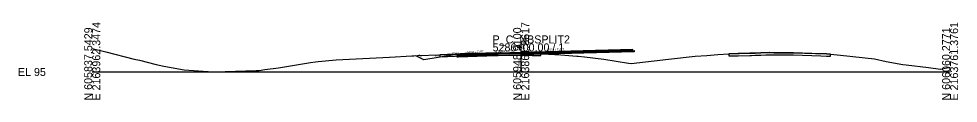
# Model space of a CAD drawing. Extents: x -26 to 1303, y -10 to 12038.
# Drawn here: x -25.7 to 302.8, y 3490.3 to 3517.4 of the extents above; entities that cross this region are included whole.
import ezdxf

# ---------------------------------------------------------------- set-up
doc = ezdxf.new("R2010")
doc.units = 0
for name, color, linetype in [('RD_GPK_XS_Cell', 7, 'Continuous'), ('RD_XS_Base', 7, 'Continuous'), ('RD_XS_ExGround', 7, 'Continuous'), ('RD_XS_ExPaveRet', 7, 'Continuous'), ('RD_XS_Greenside', 7, 'Continuous'), ('RD_XS_Pave', 7, 'Continuous'), ('RD_XS_PaveOvlay_CP', 7, 'Continuous'), ('RD_XS_TieSlope', 7, 'Continuous'), ('RD_XS_TX_Elev_EX', 7, 'Continuous'), ('RD_XS_TX_Elev_PR', 7, 'Continuous'), ('RD_XS_TX_ShdSlope', 7, 'Continuous'), ('RD_XS_TX_Slope', 7, 'Continuous')]:
    doc.layers.add(name, color=color, linetype=linetype)

msp = doc.modelspace()

# ---------------------------------------------------------------- linework, layer by layer
at = {"layer": 'RD_GPK_XS_Cell'}
for p, q in [((150, 3500), (150, 3510)), ((0, 3500), (150, 3500)), ((150, 3500), (300, 3500))]:
    msp.add_line(p, q, dxfattribs=at)
at = {"layer": 'RD_XS_Base'}
for p, q in [((128, 3505.77), (127.5, 3505.75)), ((127.5, 3505.75), (127.5, 3505.75)), ((127.5, 3505.75), (127.5, 3505.25)), ((138, 3506.17), (128, 3505.77)), ((128, 3505.77), (128, 3505.77)), ((128, 3505.27), (138, 3505.67)), ((150, 3506.48), (138, 3506.17)), ((138, 3506.17), (138, 3506.17)), ((138, 3505.67), (150, 3505.98)), ((138, 3505.67), (138, 3505.67)), ((150, 3506.48), (189.53, 3507.51)), ((189.53, 3507.01), (150, 3505.98)), ((150, 3505.98), (150, 3506.64)), ((150, 3506.64), (150, 3506.64)), ((150, 3506.64), (150, 3506.64)), ((150, 3506.64), (150, 3506.48)), ((150, 3506.48), (150, 3506.48)), ((150, 3505.98), (150, 3506.48)), ((150, 3506.48), (150, 3506.48)), ((150, 3506.48), (150, 3506.48)), ((150, 3505.98), (150, 3505.98)), ((174, 3507.11), (174, 3507.11)), ((174, 3507.11), (174, 3507.11)), ((174, 3506.61), (174, 3506.61)), ((174, 3506.61), (174, 3506.61)), ((189.03, 3507.5), (189.03, 3507.5)), ((189.53, 3507.51), (189.53, 3507.01)), ((189.53, 3507.48), (189.53, 3507.48)), ((127.5, 3505.25), (128, 3505.27)), ((128, 3505.27), (128, 3505.27))]:
    msp.add_line(p, q, dxfattribs=at)
at = {"layer": 'RD_XS_ExGround'}
msp.add_lwpolyline([(0, 3508.19), (4.75, 3507), (14.63, 3504.54), (16.49, 3504.08), (22.3, 3502.63), (25.03, 3502.08), (32.19, 3500.73), (42.14, 3500.03), (42.45, 3500.01), (42.57, 3500.01), (42.84, 3500.02), (57.27, 3500.5), (58.38, 3500.55), (60.32, 3500.84), (65.17, 3501.5), (76.32, 3503.33), (78.02, 3503.6), (79.04, 3503.71), (85.3, 3504.28), (103.91, 3505.24), (111.79, 3505.61), (112.44, 3505.67), (113.75, 3505.71), (121.56, 3506.04), (126.92, 3506.27), (130.28, 3506.41), (133.12, 3506.47), (134.35, 3506.5), (137.6, 3506.55), (139.92, 3506.58), (141.24, 3506.6), (141.76, 3506.64), (153.87, 3506.51), (156.91, 3506.46), (159.56, 3506.27), (163.84, 3505.95), (169.47, 3505.51), (169.94, 3505.5), (172.12, 3505.25), (178.85, 3504.5), (187.58, 3503.13), (188.41, 3502.99), (201.47, 3504.5), (201.47, 3504.5), (201.47, 3504.5), (210.88, 3505.5), (214.93, 3505.82), (218.73, 3506.09), (222.62, 3506.38), (229.98, 3506.55), (231.79, 3506.59), (233.83, 3506.67), (236.82, 3506.76), (236.92, 3506.76), (238.38, 3506.74), (242.46, 3506.75), (245.23, 3506.71), (256.76, 3506.33), (258.22, 3506.27), (261.63, 3505.91), (273.59, 3504.59), (277.6, 3503.72), (283.49, 3502.58), (284.6, 3502.5), (292.48, 3501.53), (296.6, 3501.04), (300, 3501.73)], dxfattribs=at)
at = {"layer": 'RD_XS_ExPaveRet'}
for points in [[(156.91, 3506.46), (156.91, 3506.46), (153.87, 3506.51), (153.87, 3506.51), (141.76, 3506.64), (141.24, 3506.6), (141.24, 3506.6), (141.24, 3506.6), (139.92, 3506.58), (139.92, 3506.58), (137.6, 3506.55), (137.6, 3506.55), (134.35, 3506.5), (134.35, 3506.5), (133.12, 3506.47), (133.12, 3506.47), (130.28, 3506.41), (126.92, 3506.27), (126.92, 3506.27), (121.56, 3506.04), (121.56, 3506.04), (121.56, 3506.04), (121.56, 3505.29), (121.56, 3505.29), (126.92, 3505.52), (126.92, 3505.52), (130.28, 3505.66), (133.12, 3505.72), (133.12, 3505.72), (134.35, 3505.75), (134.35, 3505.75), (137.6, 3505.8), (137.6, 3505.8), (139.92, 3505.83), (139.92, 3505.83), (141.24, 3505.85), (141.24, 3505.85), (141.24, 3505.85), (141.76, 3505.89), (153.87, 3505.76), (153.87, 3505.76), (156.91, 3505.71), (156.91, 3505.71), (156.91, 3505.71), (156.91, 3506.46), (156.91, 3506.46), (156.91, 3506.46)], [(156.91, 3506.46), (153.87, 3506.51), (141.76, 3506.64), (141.24, 3506.6), (139.92, 3506.58), (137.6, 3506.55), (134.35, 3506.5), (133.12, 3506.47), (130.28, 3506.41), (126.92, 3506.27), (121.56, 3506.04), (121.56, 3505.29), (126.92, 3505.52), (130.28, 3505.66), (133.12, 3505.72), (134.35, 3505.75), (137.6, 3505.8), (139.92, 3505.83), (141.24, 3505.85), (141.76, 3505.89), (153.87, 3505.76), (156.91, 3505.71), (156.91, 3505.71), (156.91, 3506.46), (156.91, 3506.46)], [(256.76, 3506.33), (254.81, 3506.4), (245.23, 3506.71), (242.97, 3506.75), (242.46, 3506.75), (241, 3506.75), (238.38, 3506.74), (237.85, 3506.75), (236.92, 3506.76), (236.86, 3506.76), (236.82, 3506.76), (235.53, 3506.72), (233.83, 3506.67), (232.43, 3506.62), (231.79, 3506.59), (230.59, 3506.56), (229.98, 3506.55), (225.86, 3506.45), (222.62, 3506.38), (222.62, 3506.08), (222.62, 3505.63), (225.86, 3505.7), (229.98, 3505.8), (230.59, 3505.81), (231.79, 3505.84), (232.43, 3505.87), (233.83, 3505.92), (235.53, 3505.97), (236.82, 3506.01), (236.86, 3506.01), (236.92, 3506.01), (237.85, 3506), (238.38, 3505.99), (241, 3506), (242.46, 3506), (242.97, 3506), (245.23, 3505.96), (254.81, 3505.65), (256.76, 3505.58), (258.22, 3505.52), (258.22, 3505.6), (258.22, 3506.27), (256.76, 3506.33)], [(256.76, 3506.33), (254.81, 3506.4), (245.23, 3506.71), (242.97, 3506.75), (242.46, 3506.75), (241, 3506.75), (238.38, 3506.74), (237.85, 3506.75), (236.92, 3506.76), (236.86, 3506.76), (236.82, 3506.76), (235.53, 3506.72), (233.83, 3506.67), (232.43, 3506.62), (231.79, 3506.59), (230.59, 3506.56), (229.98, 3506.55), (225.86, 3506.45), (222.62, 3506.38), (222.62, 3506.08), (222.62, 3505.63), (225.86, 3505.7), (229.98, 3505.8), (230.59, 3505.81), (231.79, 3505.84), (232.43, 3505.87), (233.83, 3505.92), (235.53, 3505.97), (236.82, 3506.01), (236.86, 3506.01), (236.92, 3506.01), (237.85, 3506), (238.38, 3505.99), (241, 3506), (242.46, 3506), (242.97, 3506), (245.23, 3505.96), (254.81, 3505.65), (256.76, 3505.58), (258.22, 3505.52), (258.22, 3505.6), (258.22, 3506.27), (256.76, 3506.33)]]:
    msp.add_lwpolyline(points, dxfattribs=at)
at = {"layer": 'RD_XS_Greenside'}
for p, q in [((116, 3504.26), (113.14, 3505.69)), ((126, 3505.93), (116, 3504.26))]:
    msp.add_line(p, q, dxfattribs=at)
at = {"layer": 'RD_XS_Pave'}
for p, q in [((138, 3506.49), (128, 3506.09)), ((128, 3505.93), (138, 3506.33)), ((138, 3506.33), (128, 3505.93)), ((128, 3505.77), (138, 3506.17)), ((128, 3506.09), (128, 3506.09)), ((128, 3506.09), (128, 3505.93)), ((128, 3505.93), (128, 3505.93)), ((128, 3505.93), (128, 3505.77)), ((150, 3506.8), (138, 3506.49)), ((138, 3506.33), (150, 3506.64)), ((150, 3506.64), (138, 3506.33)), ((138, 3506.49), (138, 3506.49)), ((138, 3506.17), (150, 3506.48)), ((138, 3506.33), (138, 3506.33)), ((138, 3506.33), (138, 3506.33)), ((138, 3506.17), (138, 3506.17)), ((189.03, 3507.82), (150, 3506.8)), ((189.03, 3507.66), (150, 3506.64)), ((150, 3506.48), (189.03, 3507.5)), ((150, 3506.8), (150, 3506.8)), ((150, 3506.64), (150, 3506.64)), ((150, 3506.64), (150, 3506.64)), ((150, 3506.64), (150, 3506.48)), ((150, 3506.64), (150, 3506.64)), ((150, 3506.48), (150, 3506.64)), ((150, 3506.64), (150, 3506.64)), ((150, 3506.64), (150, 3506.64)), ((150, 3506.48), (150, 3506.48)), ((150, 3506.48), (150, 3506.48)), ((174, 3507.43), (174, 3507.43)), ((174, 3507.43), (174, 3507.43)), ((174, 3507.27), (174, 3507.27)), ((174, 3507.27), (174, 3507.27)), ((174, 3507.27), (174, 3507.27)), ((174, 3507.27), (174, 3507.27)), ((174, 3507.11), (174, 3507.11)), ((174, 3507.11), (174, 3507.11)), ((189.03, 3507.66), (189.03, 3507.82)), ((189.03, 3507.82), (189.03, 3507.82)), ((189.03, 3507.5), (189.03, 3507.66)), ((189.03, 3507.66), (189.03, 3507.66))]:
    msp.add_line(p, q, dxfattribs=at)
at = {"layer": 'RD_XS_PaveOvlay_CP'}
for p, q in [((138, 3506.49), (128, 3506.09)), ((150, 3506.8), (138, 3506.49)), ((138, 3506.49), (138, 3506.49)), ((189.03, 3507.82), (150, 3506.8)), ((150, 3506.8), (150, 3506.8)), ((174, 3507.43), (174, 3507.43)), ((174, 3507.43), (174, 3507.43))]:
    msp.add_line(p, q, dxfattribs=at)
at = {"layer": 'RD_XS_TieSlope'}
msp.add_line((128, 3506.09), (126, 3505.93), dxfattribs=at)

# ---------------------------------------------------------------- texts
at = {"layer": 'RD_GPK_XS_Cell'}
for s, p in [('N 605837.5429', (0, 3490)), ('E 2163962.3474', (2.8, 3490)), ('N 605948.9100', (150, 3490)), ('E 2163861.8617', (152.8, 3490)), ('N 606060.2771', (300, 3490)), ('E 2163761.3761', (302.8, 3490))]:
    msp.add_text(s, height=2.8, rotation=90, dxfattribs=at).set_placement(p)
for s, p in [('P_C_NBSPLIT2', (140, 3510)), ('5286+00.00 / 1', (140, 3507.2)), ('EL 95', (-26, 3498.6))]:
    msp.add_text(s, height=2.8, dxfattribs=at).set_placement(p)
at = {"layer": 'RD_XS_TX_Elev_EX'}
msp.add_text('101.56', height=0.6, rotation=90, dxfattribs=at).set_placement((149.72, 3507.36))
at = {"layer": 'RD_XS_TX_Elev_PR'}
msp.add_text('101.80', height=1, rotation=90, dxfattribs=at).set_placement((151.37, 3507.16))
at = {"layer": 'RD_XS_TX_ShdSlope'}
msp.add_text('12.5:1', height=0.75, rotation=4.5739, dxfattribs=at).set_placement((125.59, 3506.07))
at = {"layer": 'RD_XS_TX_Slope'}
for s, rotation, p in [('2:1', 333.4349, (113.82, 3505.71)), ('6:1', 9.4642, (119.89, 3505.22)), ('0.040 FT./FT.', 2.2906, (130.99, 3506.5)), ('0.028 FT./FT.', 1.6039, (141, 3506.87)), ('0.028 FT./FT.', 1.6039, (159, 3507.37))]:
    msp.add_text(s, height=0.75, rotation=rotation, dxfattribs=at).set_placement(p)

doc.saveas('drawing.dxf')
